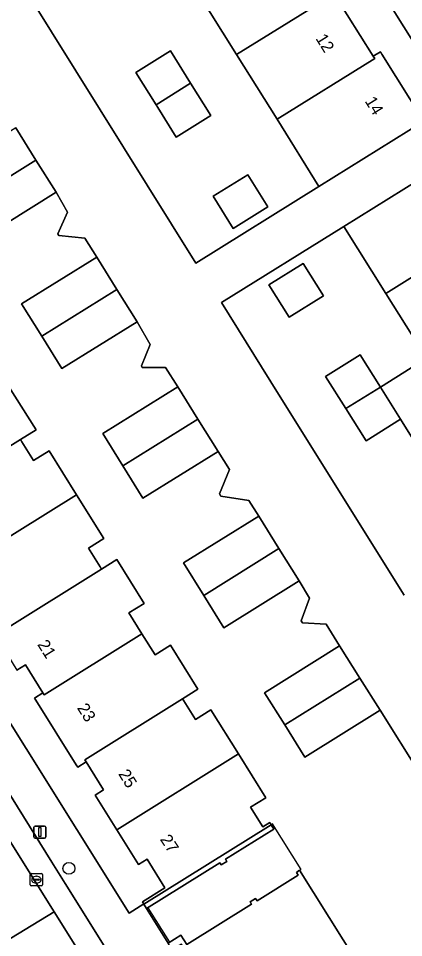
# Model space of a CAD drawing. Extents: x 159664 to 160323, y 385312 to 386115.
# Drawn here: x 159963.6 to 159995.3, y 385831.5 to 385907.3 of the extents above; entities that cross this region are included whole.
import ezdxf

# ---------------------------------------------------------------- set-up
doc = ezdxf.new("R2010")
doc.units = 0
for name, color, linetype in [('IMGEO_Boom', 7, 'Continuous'), ('IMGEO_Erf', 7, 'Continuous'), ('IMGEO_Kolk', 7, 'Continuous'), ('IMGEO_Lichtmast', 7, 'Continuous'), ('IMGEO_Pand', 7, 'Continuous'), ('IMGEO_Pand_nummerreeks', 7, 'Continuous'), ('IMGEO_Pand_overbouw', 7, 'Continuous'), ('IMGEO_Parkeervlak_open', 7, 'Continuous'), ('IMGEO_Rijbaan_lokaal_open', 7, 'Continuous'), ('IMGEO_Voetpad_open', 7, 'Continuous')]:
    doc.layers.add(name, color=color, linetype=linetype)

msp = doc.modelspace()

# ---------------------------------------------------------------- linework, layer by layer
at = {"layer": 'IMGEO_Boom'}
msp.add_circle((159967.766, 385837.192), 0.489, dxfattribs=at)
at = {"layer": 'IMGEO_Erf'}
for points in [[(159975.723, 385938.075), (159973.42, 385936.637), (159976.895, 385931.073), (159980.086, 385925.964), (159980.68, 385926.335), (159980.804, 385926.136), (159984.137, 385920.79), (159984.25, 385920.609), (159983.072, 385919.868), (159986.292, 385914.709), (159989.626, 385909.366), (159992.839, 385904.218), (159993.432, 385904.589), (159993.555, 385904.392), (159997.009, 385898.866), (159999.31, 385900.303)], [(159971.588, 385920.39), (159972.182, 385920.76), (159972.077, 385920.927), (159971.457, 385921.918), (159969.852, 385924.479), (159968.966, 385925.893), (159968.859, 385926.063), (159967.162, 385925.005), (159963.693, 385930.542), (159954.681, 385924.895), (159966.328, 385906.229), (159978.233, 385887.15), (159988.369, 385893.475), (159984.92, 385899.008), (159981.586, 385904.354), (159978.254, 385909.698), (159974.921, 385915.044)], [(159976.124, 385904.647), (159977.787, 385901.985), (159979.451, 385899.323), (159976.611, 385897.547), (159975.083, 385899.99), (159974.947, 385900.209), (159973.283, 385902.872)], [(159982.499, 385894.436), (159984.159, 385891.781), (159981.314, 385890.002), (159979.654, 385892.657)], [(159985.903, 385882.676), (159984.235, 385885.337), (159987.069, 385887.114), (159988.737, 385884.453)]]:
    msp.add_lwpolyline(points, close=True, dxfattribs=at)
for points in [[(159925.825, 385908.577), (159972.737, 385833.507), (159973.932, 385834.253), (159973.83, 385834.417), (159975.665, 385835.578), (159974.202, 385837.95), (159973.498, 385837.51), (159971.704, 385840.377), (159969.921, 385843.228), (159970.625, 385843.668), (159969.183, 385845.974), (159968.493, 385845.531), (159968.372, 385845.724), (159965.032, 385851.073), (159964.921, 385851.251), (159965.625, 385851.69), (159964.189, 385853.989), (159963.485, 385853.549)], [(159996.671, 385845.008), (159993.405, 385850.235), (159987.216, 385846.365), (159985.551, 385849.027), (159983.886, 385851.69), (159990.076, 385855.56), (159988.969, 385857.331), (159987.008, 385857.458), (159986.907, 385857.63), (159987.593, 385859.504), (159986.737, 385860.913), (159980.542, 385857.051), (159978.877, 385859.723), (159977.211, 385862.394), (159983.406, 385866.256), (159982.596, 385867.554), (159980.279, 385867.905), (159980.181, 385868.11), (159980.99, 385870.104), (159980.059, 385871.6), (159973.864, 385867.737), (159972.21, 385870.414), (159970.555, 385873.091), (159976.734, 385876.932), (159975.738, 385878.53), (159973.81, 385878.53), (159973.741, 385878.662), (159974.472, 385880.412), (159973.386, 385882.306), (159967.191, 385878.444), (159965.53, 385881.108), (159963.869, 385883.773), (159970.064, 385887.635), (159969.086, 385889.204), (159966.943, 385889.419), (159966.863, 385889.563), (159967.638, 385891.353), (159966.709, 385892.983), (159960.514, 385889.12)], [(159996.758, 385871.568), (159995.087, 385874.25), (159992.247, 385872.473), (159990.582, 385875.135), (159988.916, 385877.797), (159991.767, 385879.58), (159993.427, 385876.915), (159997.227, 385879.29), (159993.89, 385884.633), (159990.429, 385890.174), (159980.334, 385883.884), (159985.042, 385876.329), (159995.378, 385859.744)], [(159962.797, 385876.99), (159965.055, 385873.373), (159963.784, 385872.579), (159963.9, 385872.394), (159964.857, 385870.861), (159966.135, 385871.644), (159968.387, 385868.026), (159970.642, 385864.403), (159969.371, 385863.613), (159970.337, 385862.075), (159970.454, 385861.889), (159971.714, 385862.676), (159973.973, 385859.063), (159972.708, 385858.274), (159973.787, 385856.543), (159974.865, 385854.816), (159976.133, 385855.607), (159978.396, 385851.986), (159977.125, 385851.192), (159977.239, 385851.01), (159978.2, 385849.475), (159979.468, 385850.27), (159981.733, 385846.642), (159983.993, 385843.024), (159982.722, 385842.23), (159983.733, 385840.61), (159984.309, 385840.983), (159984.428, 385840.793), (159984.648, 385840.44), (159980.666, 385837.944), (159980.783, 385837.758), (159980.325, 385837.471), (159980.208, 385837.657), (159974.168, 385833.87), (159975.949, 385831.023), (159976.993, 385831.676), (159977.481, 385830.896), (159982.811, 385834.236), (159982.694, 385834.423), (159983.152, 385834.709), (159983.269, 385834.523), (159986.646, 385836.639), (159986.508, 385836.86), (159986.779, 385837.03), (159993.962, 385825.534)]]:
    msp.add_lwpolyline(points, dxfattribs=at)
at = {"layer": 'IMGEO_Kolk'}
for p, q in [((159964.586, 385835.829), (159964.586, 385836.681)), ((159964.661, 385836.755), (159965.513, 385836.755)), ((159965.074, 385836.535), (159965.099, 385836.535)), ((159965.587, 385836.681), (159965.587, 385835.829)), ((159965.513, 385835.755), (159964.661, 385835.755)), ((159964.845, 385836.249), (159964.845, 385836.261)), ((159965.283, 385836.212), (159964.885, 385836.212)), ((159964.888, 385836.298), (159965.286, 385836.298)), ((159965.097, 385835.975), (159965.072, 385835.975)), ((159965.329, 385836.261), (159965.329, 385836.249))]:
    msp.add_line(p, q, dxfattribs=at)
for points in [[(159964.586, 385835.829), (159964.586, 385836.681)], [(159964.661, 385836.755), (159965.513, 385836.755)], [(159965.587, 385836.681), (159965.587, 385835.829)], [(159965.513, 385835.755), (159964.661, 385835.755)]]:
    msp.add_lwpolyline(points, dxfattribs=at)
for centre, radius, start, end in [((159964.663, 385836.679), 0.0765, 91.55205, 178.44795), ((159964.663, 385836.679), 0.0765, 91.55205, 178.44795), ((159965.511, 385836.679), 0.0765, 1.55205, 88.44795), ((159965.511, 385836.679), 0.0765, 1.55205, 88.44795), ((159964.663, 385835.831), 0.0765, 181.55205, 268.44795), ((159964.663, 385835.831), 0.0765, 181.55205, 268.44795), ((159964.885, 385836.258), 0.0403, 85.87752, 175.75265), ((159964.882, 385836.248), 0.0366, 178.93798, 274.71019), ((159965.286, 385836.255), 0.043, 264.86636, 352.45326), ((159965.29, 385836.26), 0.0386, 1.73085, 96.63898), ((159965.511, 385835.831), 0.0765, 271.55205, 358.44795), ((159965.511, 385835.831), 0.0765, 271.55205, 358.44795)]:
    msp.add_arc(centre, radius, start, end, dxfattribs=at)
for centre, major_axis, ratio, start_param, end_param in [((159965.073, 385836.255), (-0.387, 0.002), 0.722429, 4.712389, 7.853982), ((159965.098, 385836.255), (-0.39, 0.002), 0.717154, 1.570796, 4.712389)]:
    msp.add_ellipse(centre, major_axis=major_axis, ratio=ratio, start_param=start_param, end_param=end_param, dxfattribs=at)
at = {"layer": 'IMGEO_Lichtmast'}
for p, q in [((159964.872, 385839.788), (159964.872, 385840.588)), ((159964.872, 385840.588), (159964.872, 385839.788)), ((159964.972, 385840.688), (159965.762, 385840.688)), ((159965.762, 385840.688), (159964.972, 385840.688)), ((159965.862, 385840.588), (159965.862, 385839.788)), ((159965.862, 385839.788), (159965.862, 385840.588)), ((159965.762, 385839.688), (159964.972, 385839.688)), ((159964.972, 385839.688), (159965.762, 385839.688))]:
    msp.add_line(p, q, dxfattribs=at)
msp.add_lwpolyline([(159965.292, 385840.563), (159965.442, 385840.563), (159965.442, 385839.813), (159965.292, 385839.813), (159965.292, 385840.563)], dxfattribs=at)
for centre, start, end in [((159964.972, 385840.588), 90, 180), ((159964.972, 385840.588), 90, 180), ((159965.762, 385840.588), 0, 90), ((159965.762, 385840.588), 360, 90), ((159964.972, 385839.788), 180, 270), ((159964.972, 385839.788), 180, 270), ((159965.762, 385839.788), 270, 0), ((159965.762, 385839.788), 270, 0)]:
    msp.add_arc(centre, 0.1, start, end, dxfattribs=at)
at = {"layer": 'IMGEO_Pand'}
for points in [[(159978.254, 385909.698), (159981.586, 385904.354), (159989.626, 385909.366), (159986.292, 385914.709)], [(159992.839, 385904.218), (159989.626, 385909.366), (159981.586, 385904.354), (159984.92, 385899.008), (159992.961, 385904.022)], [(159977.787, 385901.985), (159976.124, 385904.647), (159973.283, 385902.872), (159974.947, 385900.209)], [(159993.555, 385904.392), (159993.432, 385904.589), (159992.839, 385904.218), (159992.961, 385904.022), (159984.92, 385899.008), (159988.369, 385893.475), (159997.009, 385898.866)], [(159974.947, 385900.209), (159975.083, 385899.99), (159976.611, 385897.547), (159979.451, 385899.323), (159977.787, 385901.985)], [(159965.047, 385895.648), (159963.385, 385898.312), (159957.191, 385894.449), (159958.853, 385891.785)], [(159958.853, 385891.785), (159960.514, 385889.12), (159966.709, 385892.983), (159965.047, 385895.648)], [(159999.068, 385895.557), (159990.429, 385890.174), (159993.89, 385884.633), (160001.928, 385889.658), (160002.047, 385889.468), (160002.641, 385889.839), (160002.522, 385890.029)], [(159984.159, 385891.781), (159982.499, 385894.436), (159979.654, 385892.657), (159981.314, 385890.002)], [(160002.047, 385889.468), (160001.928, 385889.658), (159993.89, 385884.633), (159997.227, 385879.29), (160005.268, 385884.315)], [(159971.725, 385884.97), (159970.064, 385887.635), (159963.869, 385883.773), (159965.53, 385881.108)], [(159988.737, 385884.453), (159987.069, 385887.114), (159984.235, 385885.337), (159985.903, 385882.676)], [(159965.53, 385881.108), (159967.191, 385878.444), (159973.386, 385882.306), (159971.725, 385884.97)], [(160005.268, 385884.315), (159997.227, 385879.29), (159993.427, 385876.915), (159995.087, 385874.25), (159996.758, 385871.568), (160000.565, 385873.947), (160008.607, 385878.973)], [(159993.427, 385876.915), (159991.767, 385879.58), (159988.916, 385877.797), (159990.582, 385875.135)], [(159965.055, 385873.373), (159962.797, 385876.99), (159961.525, 385876.196), (159960.442, 385877.929), (159952.386, 385872.897), (159952.514, 385872.691), (159953.938, 385870.393), (159953.242, 385869.952), (159954.914, 385867.287), (159955.617, 385867.728), (159955.73, 385867.547), (159963.784, 385872.579)], [(159978.395, 385874.268), (159976.734, 385876.932), (159970.555, 385873.091), (159972.21, 385870.414)], [(159990.582, 385875.135), (159992.247, 385872.473), (159995.087, 385874.25), (159993.427, 385876.915)], [(159972.21, 385870.414), (159973.864, 385867.737), (159980.059, 385871.6), (159978.395, 385874.268)], [(159966.135, 385871.644), (159964.857, 385870.861), (159963.9, 385872.394), (159963.784, 385872.579), (159955.73, 385867.547), (159957.282, 385865.054), (159956.578, 385864.614), (159958.359, 385861.761), (159968.387, 385868.026)], [(159970.454, 385861.889), (159970.337, 385862.075), (159969.371, 385863.613), (159970.642, 385864.403), (159968.387, 385868.026), (159958.359, 385861.761), (159960.147, 385858.897), (159960.851, 385859.337), (159962.4, 385856.857)], [(159985.072, 385863.584), (159983.406, 385866.256), (159977.211, 385862.394), (159978.877, 385859.723)], [(159978.877, 385859.723), (159980.542, 385857.051), (159986.737, 385860.913), (159985.072, 385863.584)], [(159973.787, 385856.543), (159972.708, 385858.274), (159973.973, 385859.063), (159971.714, 385862.676), (159970.454, 385861.889), (159962.4, 385856.857), (159962.528, 385856.651), (159961.824, 385856.212), (159963.485, 385853.549), (159964.189, 385853.989), (159965.625, 385851.69), (159965.736, 385851.513)], [(159978.396, 385851.986), (159976.133, 385855.607), (159974.865, 385854.816), (159973.787, 385856.543), (159965.736, 385851.513), (159965.625, 385851.69), (159964.921, 385851.251), (159965.032, 385851.073), (159968.372, 385845.724), (159968.493, 385845.531), (159969.183, 385845.974), (159969.068, 385846.159), (159977.125, 385851.192)], [(159991.741, 385852.898), (159990.076, 385855.56), (159983.886, 385851.69), (159985.551, 385849.027)], [(159985.551, 385849.027), (159987.216, 385846.365), (159993.405, 385850.235), (159991.741, 385852.898)], [(159979.468, 385850.27), (159978.2, 385849.475), (159977.239, 385851.01), (159977.125, 385851.192), (159969.068, 385846.159), (159969.183, 385845.974), (159970.625, 385843.668), (159969.921, 385843.228), (159971.704, 385840.377), (159981.733, 385846.642)], [(159984.428, 385840.793), (159984.309, 385840.983), (159983.733, 385840.61), (159982.722, 385842.23), (159983.993, 385843.024), (159981.733, 385846.642), (159971.704, 385840.377), (159973.498, 385837.51), (159974.202, 385837.95), (159975.665, 385835.578), (159973.83, 385834.417), (159973.932, 385834.253), (159973.941, 385834.239)], [(159980.208, 385837.657), (159980.325, 385837.471), (159980.783, 385837.758), (159980.666, 385837.944), (159984.648, 385840.44), (159984.428, 385840.793), (159973.941, 385834.239), (159974.168, 385833.87)]]:
    msp.add_lwpolyline(points, close=True, dxfattribs=at)
msp.add_lwpolyline([(160013.305, 385825.116), (160008.262, 385833.182), (160007.687, 385834.102), (159993.962, 385825.534), (159986.779, 385837.03), (159986.508, 385836.86), (159986.646, 385836.639), (159983.269, 385834.523), (159983.152, 385834.709), (159982.694, 385834.423), (159982.811, 385834.236), (159977.481, 385830.896), (159976.993, 385831.676), (159975.949, 385831.023)], dxfattribs=at)
at = {"layer": 'IMGEO_Pand_overbouw'}
msp.add_lwpolyline([(159974.281, 385833.941), (159976.06, 385831.093), (159976.993, 385831.676), (159977.481, 385830.896), (159982.811, 385834.236), (159982.694, 385834.423), (159983.152, 385834.709), (159983.269, 385834.523), (159986.646, 385836.639), (159986.508, 385836.86), (159986.779, 385837.03), (159986.901, 385837.107), (159984.55, 385840.869), (159984.428, 385840.793), (159984.648, 385840.44), (159980.666, 385837.944), (159980.783, 385837.758), (159980.325, 385837.471), (159980.208, 385837.657)], close=True, dxfattribs=at)
at = {"layer": 'IMGEO_Parkeervlak_open'}
for points in [[(159909.345, 385925.272), (159966.54, 385833.611)], [(159966.363, 385837.715), (159960.317, 385847.412)], [(159967.458, 385835.954), (159966.363, 385837.715)], [(159984.172, 385809.147), (159967.458, 385835.954)], [(159966.54, 385833.611), (159978.328, 385814.729)]]:
    msp.add_lwpolyline(points, dxfattribs=at)
at = {"layer": 'IMGEO_Rijbaan_lokaal_open'}
msp.add_lwpolyline([(159961.733, 385830.677), (159966.54, 385833.611), (159909.345, 385925.272), (159909.214, 385925.452), (159904.229, 385922.375), (159904.391, 385922.078), (159904.47, 385921.952)], close=True, dxfattribs=at)
for points in [[(159966.54, 385833.611), (159961.733, 385830.677)], [(159978.328, 385814.729), (159966.54, 385833.611)]]:
    msp.add_lwpolyline(points, dxfattribs=at)
at = {"layer": 'IMGEO_Voetpad_open'}
for points in [[(159958.817, 385965.147), (159960.488, 385962.471), (159974.902, 385939.389), (159974.915, 385939.368), (159975.723, 385938.075), (159999.31, 385900.303), (160001.374, 385896.998), (160024.965, 385859.219), (160022.665, 385857.784), (160023.444, 385856.494), (160025.732, 385857.953), (160038.523, 385837.501), (160040.915, 385833.676)], [(159984.547, 385816.744), (159983.8, 385816.278), (159981.326, 385820.244), (159983.037, 385821.314), (159977.037, 385830.931), (159976.287, 385830.471), (159975.949, 385831.023), (159974.168, 385833.87), (159973.941, 385834.239), (159973.932, 385834.253), (159972.737, 385833.507), (159925.825, 385908.577), (159923.736, 385911.957), (159911.405, 385931.658), (159907.344, 385929.109)], [(159997.009, 385898.866), (159988.369, 385893.475), (159978.233, 385887.15), (159966.328, 385906.229), (159954.681, 385924.895)], [(159912.668, 385923.681), (159918.241, 385914.788), (159919.709, 385912.471), (159920.762, 385910.787), (159921.132, 385911.01), (159923.812, 385906.761), (159923.431, 385906.517), (159940.61, 385878.988), (159941.861, 385876.989), (159947.782, 385867.52), (159948.866, 385865.766), (159952.389, 385860.121), (159953.801, 385857.87), (159958.89, 385849.7), (159960.317, 385847.412), (159966.363, 385837.715), (159967.458, 385835.954), (159984.172, 385809.147)], [(159963.385, 385898.312), (159965.047, 385895.648), (159966.709, 385892.983), (159967.638, 385891.353), (159966.863, 385889.563), (159966.943, 385889.419), (159969.086, 385889.204), (159970.064, 385887.635), (159971.725, 385884.97), (159973.386, 385882.306), (159974.472, 385880.412), (159973.741, 385878.662), (159973.81, 385878.53), (159975.738, 385878.53), (159976.734, 385876.932), (159978.395, 385874.268), (159980.059, 385871.6), (159980.99, 385870.104), (159980.181, 385868.11), (159980.279, 385867.905), (159982.596, 385867.554), (159983.406, 385866.256), (159985.072, 385863.584), (159986.737, 385860.913), (159987.593, 385859.504), (159986.907, 385857.63), (159987.008, 385857.458), (159988.969, 385857.331), (159990.076, 385855.56), (159991.741, 385852.898), (159993.405, 385850.235), (159996.671, 385845.008)], [(159995.378, 385859.744), (159985.042, 385876.329), (159980.334, 385883.884), (159990.429, 385890.174), (159999.068, 385895.557)]]:
    msp.add_lwpolyline(points, dxfattribs=at)

# ---------------------------------------------------------------- texts
at = {"layer": 'IMGEO_Pand_nummerreeks'}
for s, rotation, p in [('12', 301.9651, (159988.059, 385905.682)), ('14', 302.01094, (159992.112, 385900.512)), ('21', 301.9651, (159965.133, 385855.671)), ('23', 301.98229, (159968.404, 385850.432)), ('25', 301.93073, (159971.802, 385844.986)), ('27', 303.26469, (159975.236, 385839.588))]:
    msp.add_text(s, height=1, rotation=rotation, dxfattribs=at).set_placement(p)

doc.saveas('drawing.dxf')
